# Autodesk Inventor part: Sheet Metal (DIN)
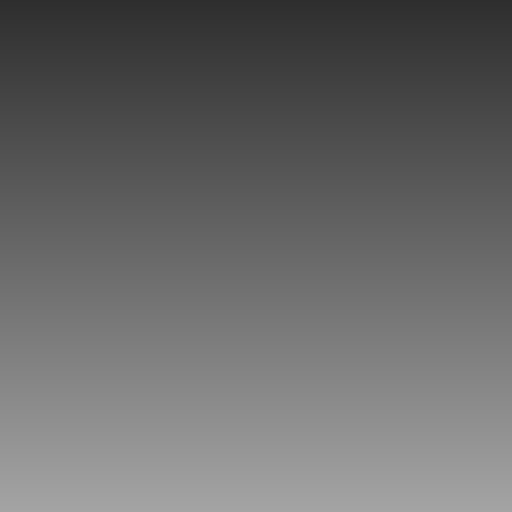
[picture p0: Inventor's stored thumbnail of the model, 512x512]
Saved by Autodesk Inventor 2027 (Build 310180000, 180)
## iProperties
Shininess: 64.0
Length Units: 11269
Angle Units: 11279
Time Units: 11290
Mass Units: 11283
Length Display Precision: 3
Angle Display Precision: 2
Compacted: True
Part Number: Sheet Metal (DIN)
Document SubType Name: Sheet Metal
Created: 2002-07
Material: Generic
Density: 1 g/cm^3
Sheet Metal Rule: Default_mm
Appearance: Default
Density: 0.0
Volumn: 0.0
Area: 0.0
PropertySet Name: Model Information
Control State: 0
Master: False
Checked Out: False
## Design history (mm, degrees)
other parameters: "Thickness" = 0.5, "BendRadius" = 0.5 (= Thickness), "BendReliefWidth" = 0.5 (= Thickness), "BendReliefDepth" = 0.25 (= 0.5 x Thickness), "CornerReliefSize" = 2 (= 4 x Thickness), "SeamGap" = 0.01, "MinimumRemnant" = 1 (= 2 x Thickness), "TransitionRadius" = 0.5 (= BendRadius), "JacobiRadiusSize" = 0.5 (= BendRadius), "GapSize" = 0.5 (= Thickness)
